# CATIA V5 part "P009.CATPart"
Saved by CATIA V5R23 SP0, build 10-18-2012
Part number: P009
Definition: Guide Du Coulisseau
Bounding box of the stored display mesh (mm): x -37 to 37, y -28 to 28, z 0 to 112
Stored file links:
  C:\wamp\www\COURS\CONCEPTION GMP1\TITRE 02-SEMESTRE 2\03-TP7-PRESSE MECANIQUE\eleve\P009.CATPart
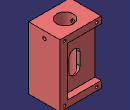
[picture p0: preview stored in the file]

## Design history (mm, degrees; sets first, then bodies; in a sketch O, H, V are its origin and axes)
Set1
  Plane1: type Offset, RefPlane xy-plane, Offset 56
  Plane2: type Offset, RefPlane yz-plane, Offset 21
  Plane3: type Offset, RefPlane Plane2, Offset 2
Body1 (main body)
  Sketch1 on xy-plane, origin (0, 0, 0), H (1, 0, 0), V (0, 1, 0)
    line L1 (-37, 28) -> (-37, -28)
    line L2 (-37, -28) -> (37, -28)
    line L3 (37, -28) -> (37, 28)
    line L4 (37, 28) -> (-37, 28)
    distance L2 L4 = 56
    distance L1 L3 = 74
    vertical: L1 V, L3 V
    horizontal: L2 H, L4 H
    symmetry: L2 L4 H, L1 L3 V
  Pad1: profile Sketch1, direction (0, 0, 1), length 112
  Sketch2 on Plane3, origin (23, 0, 0), H (0, 1, 0), V (0, 0, 1)
    line L1 (17, 100) -> (50.6441, 100)
    line L2 (50.6441, 100) -> (50.6441, 12)
    line L3 (50.6441, 12) -> (17, 12)
    line L4 (17, 12) -> (17, 100)
    point P5 (-45.428, 100)
    line L5 (-45.428, 100) -> (-17, 100)
    line L6 (-17, 100) -> (-17, 12)
    line L7 (-17, 12) -> (-45.428, 12)
    line L8 (-45.428, 12) -> (-45.428, 100)
    reference projected line E1 (-28, 0) -> (-28, 112) from edge [face of Pad1 | face of Pad1]
    reference projected line E2 (28, 0) -> (28, 112) from edge [face of Pad1 | face of Pad1]
    reference projected line E3 (-28, 112) -> (28, 112) from edge [face of Pad1 | face of Pad1]
    reference projected line E4 (-28, 0) -> (28, 0) from edge [face of Pad1 | face of Pad1]
    distance L6 E1 = 11
    distance L4 E2 = 11
    distance E3 L1 = 12
    distance L7 E4 = 12
    distance L3 H = 12
    horizontal: L1 H, L3 H, L5 H, L7 H
    vertical: L2 V, L4 V, L6 V, L8 V
    coincidence: P5 L1
  Pocket1: profile Sketch2, direction (-1, 0, 0), through (limit type 6)
  Sketch3 on face of Pocket1, origin (0, -17, 0), H (1, 0, 0), V (0, 0, 1)
    construction line L1 (0, 64) -> (0, 43)
    point P1 (0, 64)
    point P2 (0, 43)
    line L2 (10, 64) -> (10, 43)
    line L3 (-10, 43) -> (-10, 64)
    arc A1 centre (0, 43) radius 10 from (10, 43) to (-10, 43) cw
    arc A2 centre (0, 64) radius 10 from (-10, 64) to (10, 64) cw
    reference projected line E1 (23, 12) -> (-37, 12) from edge [face of Pocket1 | face of Pad1]
    distance L3 L2 = 20
    distance P1 P2 = 21
    distance A1 E1 = 21
    coincidence: P1 V
    vertical: L1 V
    tangency: A1 L2, A2 L2, A1 L3, A2 L3
    parallelism: L1 L2
  Pocket2: profile Sketch3, direction (0, 1, 0), through (limit type 3)
  Sketch4 on face of Pad1, origin (22.2, -7.25, 112), H (1, 0, 0), V (0, 1, 0)
    point P1 (-22.2, 7.25)
    reference intersected line E1 through (-22.2, 0) direction (0, 1) from yz-plane
    reference intersected line E2 through (0, 7.25) direction (-1, 0) from zx-plane
    coincidence: E1 P1, P1 E2
  Hole1: placed by Sketch4, at (0, 0, 112) direction (0, 0, -1), diameter 30, up to face of Pad1
  Sketch5 on face of Pad1, origin (-14.941, 28, 105), H (1, 0, 0), V (0, 0, -1)
    point P1 (-14.059, -1)
    reference projected line E1 (-22.059, 105) -> (-22.059, -7) from edge [face of Pad1 | face of Pad1]
    reference projected line E2 (51.941, -7) -> (-22.059, -7) from edge [face of Pad1 | face of Pad1]
    distance P1 E1 = 8
    distance P1 E2 = 6
  Hole2: placed by Sketch5, at (-29, 28, 106) direction (0, -1, 0), diameter 4.917, depth 13, V-bottom angle 120, threaded "M6", thread diameter 6, thread depth 9, pitch 1
  RectPattern1: of Hole2, direction 1 instances 2, spacing 58, along face of Pad1 reversed, direction 2 instances 2, spacing 100, along face of Pad1 reversed
  Sketch6 on face of Pad1, origin (-13.6134, -28, 105), H (1, 0, 0), V (0, 0, 1)
    point P1 (-15.3866, 1)
    reference projected line E1 (-23.3866, 7) -> (50.6134, 7) from edge [face of Pad1 | face of Pad1]
    reference projected line E2 (-23.3866, -105) -> (-23.3866, 7) from edge [face of Pad1 | face of Pad1]
    distance P1 E1 = 6
    distance P1 E2 = 8
  Hole3: placed by Sketch6, at (-29, -28, 106) direction (0, 1, 0), diameter 4.917, depth 13, V-bottom angle 120, threaded "M6", thread diameter 6, thread depth 9, pitch 1
  RectPattern2: of Hole3, direction 1 instances 2, spacing 58, along face of Pad1, direction 2 instances 2, spacing 100, along face of Pad1 reversed
  Sketch7 on zx-plane, origin (0, 0, 0), H (-1, 0, 0), V (0, 0, 1)
    line L1 (-37, 100) -> (17, 100)
    line L2 (17, 100) -> (17, 104)
    line L3 (17, 104) -> (-17, 104)
    line L4 (-17, 104) -> (-17, 103)
    line L5 (-17, 103) -> (-37, 103)
    line L6 (-37, 103) -> (-37, 100)
    reference intersected line E1 (-37, 0) -> (-37, 112) from face of Pad1
    reference intersected line E2 through (0, 100) direction (-1, 0) from face of Pocket1
    axis line L7 (109.7703, 100) -> (-93.0181, 100)
    point P7 (109.7703, 100)
    length L5 = 20
    length L3 = 34
    length L6 = 3
    length L2 = 4
    horizontal: L1 H, L3 H, L5 H, L7 H
    vertical: L2 V, L4 V, L6 V
    coincidence: L6 E1, L1 E2, P7 L1
  Groove1: profile Sketch7, axis Sketch7.L7, angle 360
